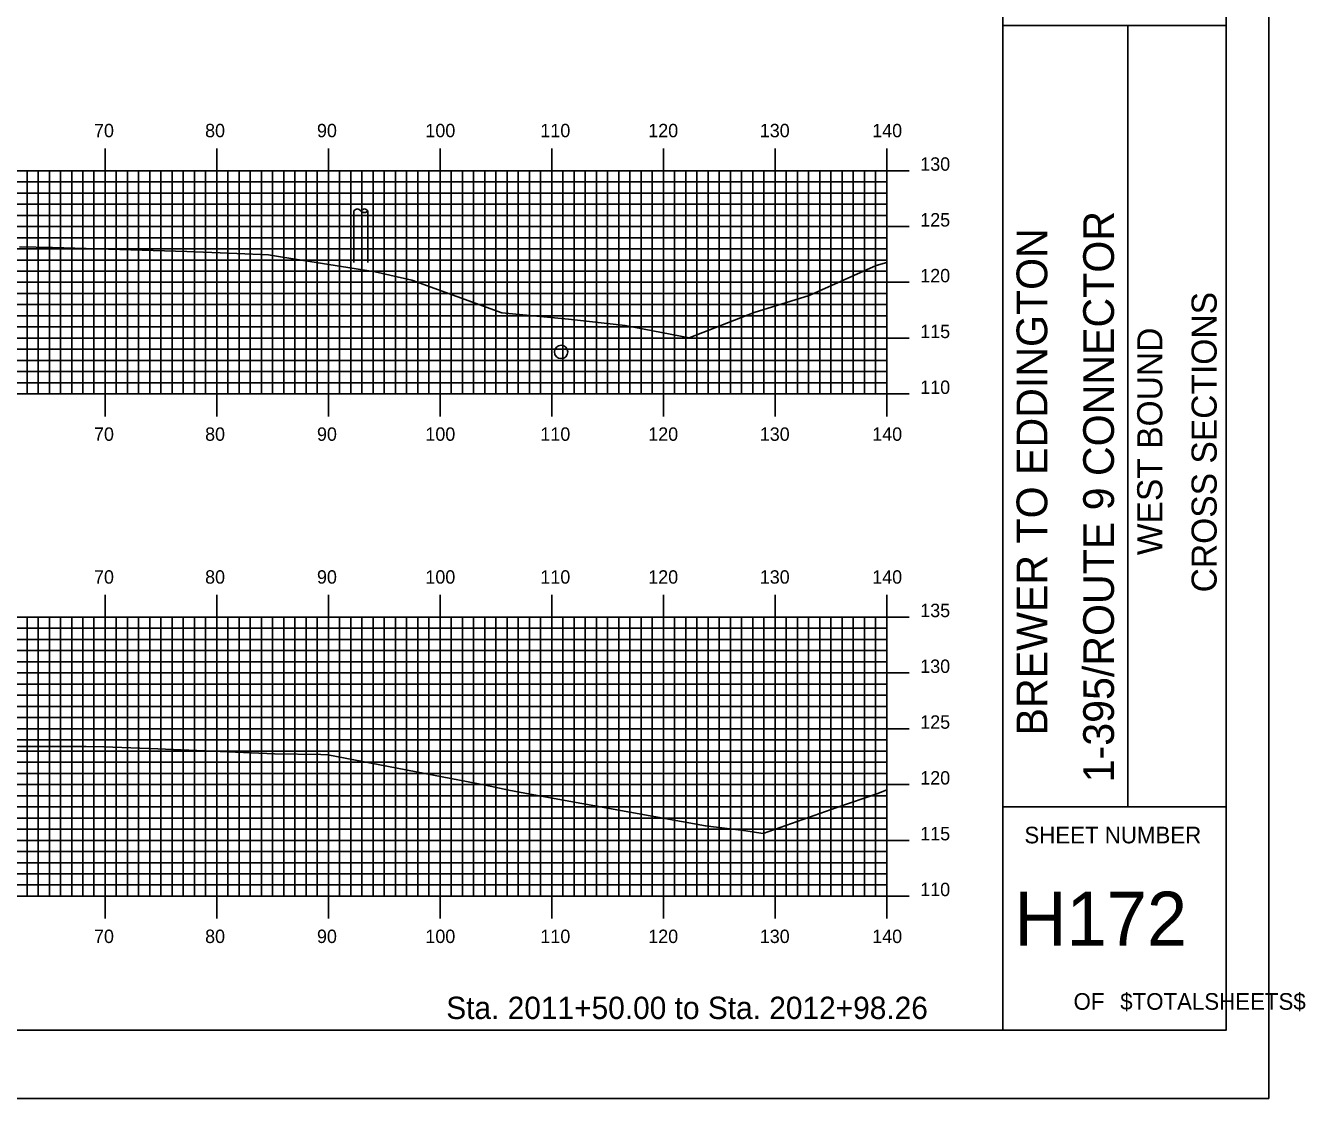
# Model space of a CAD drawing. Extents: x 853894 to 854237, y 366605 to 366825.
# Drawn here: x 854122.4 to 854237, y 366604.9 to 366701.1 of the extents above; entities that cross this region are included whole.
import ezdxf

# ---------------------------------------------------------------- set-up
doc = ezdxf.new("R2010")
doc.units = 0
for name, color, linetype in [('BORDER', 7, 'Continuous'), ('D_Drainage_Underdrain', 7, 'Continuous'), ('H_V ANNOTATION', 7, 'Continuous'), ('M_Roadway_Centerline', 7, 'Continuous'), ('MAJOR', 7, 'Continuous'), ('MINOR', 7, 'Continuous'), ('PLOT BOUNDARY', 7, 'Continuous'), ('S_Drainage_Invert', 7, 'Continuous'), ('S_Roadway_Centerline', 7, 'Continuous'), ('S_Utilities_Pole_StreetLight', 7, 'Continuous')]:
    doc.layers.add(name, color=color, linetype=linetype)

msp = doc.modelspace()

# ---------------------------------------------------------------- linework, layer by layer
at = {"layer": 'BORDER'}
for p, q in [((854209.93, 366611.06), (854209.93, 366821.06)), ((854209.93, 366701.06), (854229.93, 366701.06)), ((854221.11, 366631.06), (854221.11, 366701.06)), ((854209.93, 366631.06), (854229.93, 366631.06))]:
    msp.add_line(p, q, dxfattribs=at)
msp.add_lwpolyline([(853909.93, 366611.06), (854229.93, 366611.06), (854229.93, 366821.06), (853909.93, 366821.06)], close=True, dxfattribs=at)
at = {"layer": 'D_Drainage_Underdrain'}
msp.add_line((854199.53, 366673.06), (854199.53, 366676.56), dxfattribs=at)
at = {"layer": 'MAJOR'}
for p, q in [((854129.53, 366690.06), (854129.53, 366688.06)), ((854139.53, 366690.06), (854139.53, 366688.06)), ((854149.53, 366690.06), (854149.53, 366688.06)), ((854159.53, 366690.06), (854159.53, 366688.06)), ((854169.53, 366690.06), (854169.53, 366688.06)), ((854179.53, 366690.06), (854179.53, 366688.06)), ((854189.53, 366690.06), (854189.53, 366688.06)), ((854199.53, 366690.06), (854199.53, 366688.06)), ((853919.53, 366688.06), (854199.53, 366688.06)), ((853919.53, 366688.06), (854199.53, 366688.06)), ((854129.53, 366668.06), (854129.53, 366688.06)), ((854139.53, 366668.06), (854139.53, 366688.06)), ((854149.53, 366668.06), (854149.53, 366688.06)), ((854159.53, 366668.06), (854159.53, 366688.06)), ((854169.53, 366668.06), (854169.53, 366688.06)), ((854179.53, 366668.06), (854179.53, 366688.06)), ((854189.53, 366668.06), (854189.53, 366688.06)), ((854201.53, 366688.06), (854197.53, 366688.06)), ((854199.53, 366668.06), (854199.53, 366688.06)), ((854199.53, 366668.06), (854199.53, 366688.06)), ((853919.53, 366683.06), (854199.53, 366683.06)), ((854201.53, 366683.06), (854197.53, 366683.06)), ((853919.53, 366678.06), (854199.53, 366678.06)), ((854201.53, 366678.06), (854197.53, 366678.06)), ((853919.53, 366673.06), (854199.53, 366673.06)), ((854201.53, 366673.06), (854197.53, 366673.06)), ((853919.53, 366668.06), (854199.53, 366668.06)), ((853919.53, 366668.06), (854199.53, 366668.06)), ((854129.53, 366666.05), (854129.53, 366668.06)), ((854139.53, 366666.05), (854139.53, 366668.06)), ((854149.53, 366666.05), (854149.53, 366668.06)), ((854159.53, 366666.05), (854159.53, 366668.06)), ((854169.53, 366666.05), (854169.53, 366668.06)), ((854179.53, 366666.05), (854179.53, 366668.06)), ((854189.53, 366666.05), (854189.53, 366668.06)), ((854201.53, 366668.06), (854197.53, 366668.06)), ((854199.53, 366666.05), (854199.53, 366668.06)), ((854129.53, 366650.06), (854129.53, 366648.06)), ((854139.53, 366650.06), (854139.53, 366648.06)), ((854149.53, 366650.06), (854149.53, 366648.06)), ((854159.53, 366650.06), (854159.53, 366648.06)), ((854169.53, 366650.06), (854169.53, 366648.06)), ((854179.53, 366650.06), (854179.53, 366648.06)), ((854189.53, 366650.06), (854189.53, 366648.06)), ((854199.53, 366650.06), (854199.53, 366648.06)), ((853919.53, 366648.06), (854199.53, 366648.06)), ((853919.53, 366648.06), (854199.53, 366648.06)), ((854129.53, 366623.06), (854129.53, 366648.06)), ((854139.53, 366623.06), (854139.53, 366648.06)), ((854149.53, 366623.06), (854149.53, 366648.06)), ((854159.53, 366623.06), (854159.53, 366648.06)), ((854169.53, 366623.06), (854169.53, 366648.06)), ((854179.53, 366623.06), (854179.53, 366648.06)), ((854189.53, 366623.06), (854189.53, 366648.06)), ((854201.53, 366648.06), (854197.53, 366648.06)), ((854199.53, 366623.06), (854199.53, 366648.06)), ((854199.53, 366623.06), (854199.53, 366648.06)), ((853919.53, 366643.06), (854199.53, 366643.06)), ((854201.53, 366643.06), (854197.53, 366643.06)), ((853919.53, 366638.06), (854199.53, 366638.06)), ((854201.53, 366638.06), (854197.53, 366638.06)), ((853919.53, 366633.06), (854199.53, 366633.06)), ((854201.53, 366633.06), (854197.53, 366633.06)), ((853919.53, 366628.06), (854199.53, 366628.06)), ((854201.53, 366628.06), (854197.53, 366628.06)), ((853919.53, 366623.06), (854199.53, 366623.06)), ((853919.53, 366623.06), (854199.53, 366623.06)), ((854129.53, 366621.05), (854129.53, 366623.06)), ((854139.53, 366621.05), (854139.53, 366623.06)), ((854149.53, 366621.05), (854149.53, 366623.06)), ((854159.53, 366621.05), (854159.53, 366623.06)), ((854169.53, 366621.05), (854169.53, 366623.06)), ((854179.53, 366621.05), (854179.53, 366623.06)), ((854189.53, 366621.05), (854189.53, 366623.06)), ((854201.53, 366623.06), (854197.53, 366623.06)), ((854199.53, 366621.05), (854199.53, 366623.06))]:
    msp.add_line(p, q, dxfattribs=at)
at = {"layer": 'MINOR'}
for p, q in [((854122.53, 366668.06), (854122.53, 366688.06)), ((854123.53, 366668.06), (854123.53, 366688.06)), ((854124.53, 366668.06), (854124.53, 366688.06)), ((854125.53, 366668.06), (854125.53, 366688.06)), ((854126.53, 366668.06), (854126.53, 366688.06)), ((854127.53, 366668.06), (854127.53, 366688.06)), ((854128.53, 366668.06), (854128.53, 366688.06)), ((854130.53, 366668.06), (854130.53, 366688.06)), ((854131.53, 366668.06), (854131.53, 366688.06)), ((854132.53, 366668.06), (854132.53, 366688.06)), ((854133.53, 366668.06), (854133.53, 366688.06)), ((854134.53, 366668.06), (854134.53, 366688.06)), ((854135.53, 366668.06), (854135.53, 366688.06)), ((854136.53, 366668.06), (854136.53, 366688.06)), ((854137.53, 366668.06), (854137.53, 366688.06)), ((854138.53, 366668.06), (854138.53, 366688.06)), ((854140.53, 366668.06), (854140.53, 366688.06)), ((854141.53, 366668.06), (854141.53, 366688.06)), ((854142.53, 366668.06), (854142.53, 366688.06)), ((854143.53, 366668.06), (854143.53, 366688.06)), ((854144.53, 366668.06), (854144.53, 366688.06)), ((854145.53, 366668.06), (854145.53, 366688.06)), ((854146.53, 366668.06), (854146.53, 366688.06)), ((854147.53, 366668.06), (854147.53, 366688.06)), ((854148.53, 366668.06), (854148.53, 366688.06)), ((854150.53, 366668.06), (854150.53, 366688.06)), ((854151.53, 366668.06), (854151.53, 366688.06)), ((854152.53, 366668.06), (854152.53, 366688.06)), ((854153.53, 366668.06), (854153.53, 366688.06)), ((854154.53, 366668.06), (854154.53, 366688.06)), ((854155.53, 366668.06), (854155.53, 366688.06)), ((854156.53, 366668.06), (854156.53, 366688.06)), ((854157.53, 366668.06), (854157.53, 366688.06)), ((854158.53, 366668.06), (854158.53, 366688.06)), ((854160.53, 366668.06), (854160.53, 366688.06)), ((854161.53, 366668.06), (854161.53, 366688.06)), ((854162.53, 366668.06), (854162.53, 366688.06)), ((854163.53, 366668.06), (854163.53, 366688.06)), ((854164.53, 366668.06), (854164.53, 366688.06)), ((854165.53, 366668.06), (854165.53, 366688.06)), ((854166.53, 366668.06), (854166.53, 366688.06)), ((854167.53, 366668.06), (854167.53, 366688.06)), ((854168.53, 366668.06), (854168.53, 366688.06)), ((854170.53, 366668.06), (854170.53, 366688.06)), ((854171.53, 366668.06), (854171.53, 366688.06)), ((854172.53, 366668.06), (854172.53, 366688.06)), ((854173.53, 366668.06), (854173.53, 366688.06)), ((854174.53, 366668.06), (854174.53, 366688.06)), ((854175.53, 366668.06), (854175.53, 366688.06)), ((854176.53, 366668.06), (854176.53, 366688.06)), ((854177.53, 366668.06), (854177.53, 366688.06)), ((854178.53, 366668.06), (854178.53, 366688.06)), ((854180.53, 366668.06), (854180.53, 366688.06)), ((854181.53, 366668.06), (854181.53, 366688.06)), ((854182.53, 366668.06), (854182.53, 366688.06)), ((854183.53, 366668.06), (854183.53, 366688.06)), ((854184.53, 366668.06), (854184.53, 366688.06)), ((854185.53, 366668.06), (854185.53, 366688.06)), ((854186.53, 366668.06), (854186.53, 366688.06)), ((854187.53, 366668.06), (854187.53, 366688.06)), ((854188.53, 366668.06), (854188.53, 366688.06)), ((854190.53, 366668.06), (854190.53, 366688.06)), ((854191.53, 366668.06), (854191.53, 366688.06)), ((854192.53, 366668.06), (854192.53, 366688.06)), ((854193.53, 366668.06), (854193.53, 366688.06)), ((854194.53, 366668.06), (854194.53, 366688.06)), ((854195.53, 366668.06), (854195.53, 366688.06)), ((854196.53, 366668.06), (854196.53, 366688.06)), ((854197.53, 366668.06), (854197.53, 366688.06)), ((854198.53, 366668.06), (854198.53, 366688.06)), ((853919.53, 366687.06), (854199.53, 366687.06)), ((854199.53, 366687.06), (854197.53, 366687.06)), ((853919.53, 366686.06), (854199.53, 366686.06)), ((854199.53, 366686.06), (854197.53, 366686.06)), ((853919.53, 366685.06), (854199.53, 366685.06)), ((854199.53, 366685.06), (854197.53, 366685.06)), ((853919.53, 366684.06), (854199.53, 366684.06)), ((854199.53, 366684.06), (854197.53, 366684.06)), ((853919.53, 366682.06), (854199.53, 366682.06)), ((854199.53, 366682.06), (854197.53, 366682.06)), ((853919.53, 366681.06), (854199.53, 366681.06)), ((854199.53, 366681.06), (854197.53, 366681.06)), ((853919.53, 366680.06), (854199.53, 366680.06)), ((854199.53, 366680.06), (854197.53, 366680.06)), ((853919.53, 366679.06), (854199.53, 366679.06)), ((854199.53, 366679.06), (854197.53, 366679.06)), ((853919.53, 366677.06), (854199.53, 366677.06)), ((854199.53, 366677.06), (854197.53, 366677.06)), ((853919.53, 366676.06), (854199.53, 366676.06)), ((853919.53, 366675.06), (854199.53, 366675.06)), ((854199.53, 366676.06), (854197.53, 366676.06)), ((854199.53, 366675.06), (854197.53, 366675.06)), ((853919.53, 366674.06), (854199.53, 366674.06)), ((854199.53, 366674.06), (854197.53, 366674.06)), ((853919.53, 366672.06), (854199.53, 366672.06)), ((854199.53, 366672.06), (854197.53, 366672.06)), ((853919.53, 366671.06), (854199.53, 366671.06)), ((854199.53, 366671.06), (854197.53, 366671.06)), ((853919.53, 366670.06), (854199.53, 366670.06)), ((854199.53, 366670.06), (854197.53, 366670.06)), ((853919.53, 366669.06), (854199.53, 366669.06)), ((854199.53, 366669.06), (854197.53, 366669.06)), ((854122.53, 366623.06), (854122.53, 366648.06)), ((854123.53, 366623.06), (854123.53, 366648.06)), ((854124.53, 366623.06), (854124.53, 366648.06)), ((854125.53, 366623.06), (854125.53, 366648.06)), ((854126.53, 366623.06), (854126.53, 366648.06)), ((854127.53, 366623.06), (854127.53, 366648.06)), ((854128.53, 366623.06), (854128.53, 366648.06)), ((854130.53, 366623.06), (854130.53, 366648.06)), ((854131.53, 366623.06), (854131.53, 366648.06)), ((854132.53, 366623.06), (854132.53, 366648.06)), ((854133.53, 366623.06), (854133.53, 366648.06)), ((854134.53, 366623.06), (854134.53, 366648.06)), ((854135.53, 366623.06), (854135.53, 366648.06)), ((854136.53, 366623.06), (854136.53, 366648.06)), ((854137.53, 366623.06), (854137.53, 366648.06)), ((854138.53, 366623.06), (854138.53, 366648.06)), ((854140.53, 366623.06), (854140.53, 366648.06)), ((854141.53, 366623.06), (854141.53, 366648.06)), ((854142.53, 366623.06), (854142.53, 366648.06)), ((854143.53, 366623.06), (854143.53, 366648.06)), ((854144.53, 366623.06), (854144.53, 366648.06)), ((854145.53, 366623.06), (854145.53, 366648.06)), ((854146.53, 366623.06), (854146.53, 366648.06)), ((854147.53, 366623.06), (854147.53, 366648.06)), ((854148.53, 366623.06), (854148.53, 366648.06)), ((854150.53, 366623.06), (854150.53, 366648.06)), ((854151.53, 366623.06), (854151.53, 366648.06)), ((854152.53, 366623.06), (854152.53, 366648.06)), ((854153.53, 366623.06), (854153.53, 366648.06)), ((854154.53, 366623.06), (854154.53, 366648.06)), ((854155.53, 366623.06), (854155.53, 366648.06)), ((854156.53, 366623.06), (854156.53, 366648.06)), ((854157.53, 366623.06), (854157.53, 366648.06)), ((854158.53, 366623.06), (854158.53, 366648.06)), ((854160.53, 366623.06), (854160.53, 366648.06)), ((854161.53, 366623.06), (854161.53, 366648.06)), ((854162.53, 366623.06), (854162.53, 366648.06)), ((854163.53, 366623.06), (854163.53, 366648.06)), ((854164.53, 366623.06), (854164.53, 366648.06)), ((854165.53, 366623.06), (854165.53, 366648.06)), ((854166.53, 366623.06), (854166.53, 366648.06)), ((854167.53, 366623.06), (854167.53, 366648.06)), ((854168.53, 366623.06), (854168.53, 366648.06)), ((854170.53, 366623.06), (854170.53, 366648.06)), ((854171.53, 366623.06), (854171.53, 366648.06)), ((854172.53, 366623.06), (854172.53, 366648.06)), ((854173.53, 366623.06), (854173.53, 366648.06)), ((854174.53, 366623.06), (854174.53, 366648.06)), ((854175.53, 366623.06), (854175.53, 366648.06)), ((854176.53, 366623.06), (854176.53, 366648.06)), ((854177.53, 366623.06), (854177.53, 366648.06)), ((854178.53, 366623.06), (854178.53, 366648.06)), ((854180.53, 366623.06), (854180.53, 366648.06)), ((854181.53, 366623.06), (854181.53, 366648.06)), ((854182.53, 366623.06), (854182.53, 366648.06)), ((854183.53, 366623.06), (854183.53, 366648.06)), ((854184.53, 366623.06), (854184.53, 366648.06)), ((854185.53, 366623.06), (854185.53, 366648.06)), ((854186.53, 366623.06), (854186.53, 366648.06)), ((854187.53, 366623.06), (854187.53, 366648.06)), ((854188.53, 366623.06), (854188.53, 366648.06)), ((854190.53, 366623.06), (854190.53, 366648.06)), ((854191.53, 366623.06), (854191.53, 366648.06)), ((854192.53, 366623.06), (854192.53, 366648.06)), ((854193.53, 366623.06), (854193.53, 366648.06)), ((854194.53, 366623.06), (854194.53, 366648.06)), ((854195.53, 366623.06), (854195.53, 366648.06)), ((854196.53, 366623.06), (854196.53, 366648.06)), ((854197.53, 366623.06), (854197.53, 366648.06)), ((854198.53, 366623.06), (854198.53, 366648.06)), ((853919.53, 366647.06), (854199.53, 366647.06)), ((854199.53, 366647.06), (854197.53, 366647.06)), ((853919.53, 366646.06), (854199.53, 366646.06)), ((854199.53, 366646.06), (854197.53, 366646.06)), ((853919.53, 366645.06), (854199.53, 366645.06)), ((854199.53, 366645.06), (854197.53, 366645.06)), ((853919.53, 366644.06), (854199.53, 366644.06)), ((854199.53, 366644.06), (854197.53, 366644.06)), ((853919.53, 366642.06), (854199.53, 366642.06)), ((854199.53, 366642.06), (854197.53, 366642.06)), ((853919.53, 366641.06), (854199.53, 366641.06)), ((854199.53, 366641.06), (854197.53, 366641.06)), ((853919.53, 366640.06), (854199.53, 366640.06)), ((854199.53, 366640.06), (854197.53, 366640.06)), ((853919.53, 366639.06), (854199.53, 366639.06)), ((854199.53, 366639.06), (854197.53, 366639.06)), ((853919.53, 366637.06), (854199.53, 366637.06)), ((853919.53, 366636.06), (854199.53, 366636.06)), ((854199.53, 366637.06), (854197.53, 366637.06)), ((854199.53, 366636.06), (854197.53, 366636.06)), ((853919.53, 366635.06), (854199.53, 366635.06)), ((854199.53, 366635.06), (854197.53, 366635.06)), ((853919.53, 366634.06), (854199.53, 366634.06)), ((854199.53, 366634.06), (854197.53, 366634.06)), ((853919.53, 366632.06), (854199.53, 366632.06)), ((854199.53, 366632.06), (854197.53, 366632.06)), ((853919.53, 366631.06), (854199.53, 366631.06)), ((854199.53, 366631.06), (854197.53, 366631.06)), ((853919.53, 366630.06), (854199.53, 366630.06)), ((854199.53, 366630.06), (854197.53, 366630.06)), ((853919.53, 366629.06), (854199.53, 366629.06)), ((854199.53, 366629.06), (854197.53, 366629.06)), ((853919.53, 366627.06), (854199.53, 366627.06)), ((854199.53, 366627.06), (854197.53, 366627.06)), ((853919.53, 366626.06), (854199.53, 366626.06)), ((854199.53, 366626.06), (854197.53, 366626.06)), ((853919.53, 366625.06), (854199.53, 366625.06)), ((854199.53, 366625.06), (854197.53, 366625.06)), ((853919.53, 366624.06), (854199.53, 366624.06)), ((854199.53, 366624.06), (854197.53, 366624.06))]:
    msp.add_line(p, q, dxfattribs=at)
at = {"layer": 'PLOT BOUNDARY'}
msp.add_lwpolyline([(853893.74, 366604.94), (854233.74, 366604.94), (854233.74, 366824.94), (853893.74, 366824.94)], close=True, dxfattribs=at)
at = {"layer": 'S_Drainage_Invert'}
msp.add_circle((854170.37, 366671.82), 0.6, dxfattribs=at)
at = {"layer": 'S_Roadway_Centerline'}
for points in [[(854121.87, 366681.24), (854124.81, 366681.19), (854136.83, 366680.83), (854141.32, 366680.65), (854144.15, 366680.53), (854145.41, 366680.32), (854153.71, 366678.99), (854157.01, 366678.24), (854165.07, 366675.32), (854171.04, 366674.75), (854176.09, 366674.2), (854181.83, 366673.09), (854187.67, 366675.37), (854192.57, 366676.87), (854198.57, 366679.57), (854199.53, 366679.84)], [(854121.26, 366636.48), (854123.11, 366636.48), (854127.84, 366636.46), (854129.4, 366636.44), (854134.26, 366636.25), (854144.69, 366635.82), (854148.85, 366635.74), (854149.46, 366635.71), (854163.6, 366632.99), (854165.68, 366632.57), (854167.58, 366632.19), (854183.29, 366629.35), (854186.71, 366628.93), (854188.47, 366628.67), (854195.06, 366631), (854198.72, 366632.27), (854199.53, 366632.6)]]:
    msp.add_lwpolyline(points, dxfattribs=at)
at = {"layer": 'S_Utilities_Pole_StreetLight'}
for p, q in [((854151.81, 366684.47), (854151.96, 366684.58)), ((854151.81, 366679.85), (854151.81, 366684.47)), ((854152.28, 366684.58), (854152.43, 366684.47)), ((854152.59, 366684.58), (854152.43, 366684.47)), ((854152.43, 366684.47), (854152.59, 366684.36)), ((854153.06, 366684.47), (854152.9, 366684.58)), ((854152.9, 366684.36), (854153.06, 366684.47)), ((854153.06, 366679.85), (854153.06, 366684.47))]:
    msp.add_line(p, q, dxfattribs=at)
for centre, start, end in [((854152.12, 366684.36), 90, 125.2644), ((854152.12, 366684.36), 54.7356, 90), ((854152.75, 366684.36), 90, 125.2644), ((854152.75, 366684.58), 234.7356, 270), ((854152.75, 366684.36), 54.7356, 90), ((854152.75, 366684.58), 270, 305.2644)]:
    msp.add_arc(centre, 0.271, start, end, dxfattribs=at)

# ---------------------------------------------------------------- texts
at = {"layer": 'BORDER'}
for s, height, p in [('1-395/ROUTE 9 CONNECTOR', 2.7557, (854219.88, 366633.26)), ('BREWER TO EDDINGTON', 2.7557, (854213.91, 366637.46)), ('CROSS SECTIONS', 2.25, (854229.08, 366650.28)), ('WEST BOUND', 2.25, (854224.21, 366653.61))]:
    msp.add_text(s, height=height, rotation=90, dxfattribs=at).set_placement(p)
for s, height, p in [('SHEET NUMBER', 1.4905, (854211.86, 366627.79)), ('H172', 4.839, (854210.96, 366618.62)), ('OF', 1.491, (854216.26, 366612.88)), ('$TOTALSHEETS$', 1.4905, (854220.44, 366612.88))]:
    msp.add_text(s, height=height, dxfattribs=at).set_placement(p)
at = {"layer": 'H_V ANNOTATION'}
for s, height, p in [('70', 1.2, (854128.53, 366691.06)), ('80', 1.2, (854138.48, 366691.06)), ('90', 1.2, (854148.5, 366691.06)), ('100', 1.2, (854158.21, 366691.06)), ('110', 1.2, (854168.51, 366691.06)), ('120', 1.2, (854178.17, 366691.06)), ('130', 1.2, (854188.16, 366691.06)), ('140', 1.2, (854198.23, 366691.06)), ('130', 1.2, (854202.53, 366688.06)), ('125', 1.2, (854202.53, 366683.06)), ('120', 1.2, (854202.53, 366678.06)), ('115', 1.2, (854202.53, 366673.06)), ('110', 1.2, (854202.53, 366668.06)), ('70', 1.2, (854128.53, 366663.86)), ('80', 1.2, (854138.48, 366663.86)), ('90', 1.2, (854148.5, 366663.86)), ('100', 1.2, (854158.21, 366663.86)), ('110', 1.2, (854168.51, 366663.86)), ('120', 1.2, (854178.17, 366663.86)), ('130', 1.2, (854188.16, 366663.86)), ('140', 1.2, (854198.23, 366663.86)), ('70', 1.2, (854128.53, 366651.06)), ('80', 1.2, (854138.48, 366651.06)), ('90', 1.2, (854148.5, 366651.06)), ('100', 1.2, (854158.21, 366651.06)), ('110', 1.2, (854168.51, 366651.06)), ('120', 1.2, (854178.17, 366651.06)), ('130', 1.2, (854188.16, 366651.06)), ('140', 1.2, (854198.23, 366651.06)), ('135', 1.2, (854202.53, 366648.06)), ('130', 1.2, (854202.53, 366643.06)), ('125', 1.2, (854202.53, 366638.06)), ('120', 1.2, (854202.53, 366633.06)), ('115', 1.2, (854202.53, 366628.06)), ('110', 1.2, (854202.53, 366623.06)), ('70', 1.2, (854128.53, 366618.86)), ('80', 1.2, (854138.48, 366618.86)), ('90', 1.2, (854148.5, 366618.86)), ('100', 1.2, (854158.21, 366618.86)), ('110', 1.2, (854168.51, 366618.86)), ('120', 1.2, (854178.17, 366618.86)), ('130', 1.2, (854188.16, 366618.86)), ('140', 1.2, (854198.23, 366618.86)), ('Sta. 2011+50.00 to Sta. 2012+98.26', 2.0004, (854160.08, 366612.05))]:
    msp.add_text(s, height=height, dxfattribs=at).set_placement(p)
at = {"layer": 'M_Roadway_Centerline'}
for s, p in [('C', (854123.1, 366636.48)), ('L', (854123.11, 366636.48))]:
    msp.add_text(s, height=0.0146, dxfattribs=at).set_placement(p)

doc.saveas('drawing.dxf')
